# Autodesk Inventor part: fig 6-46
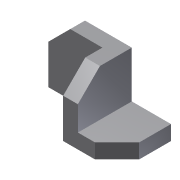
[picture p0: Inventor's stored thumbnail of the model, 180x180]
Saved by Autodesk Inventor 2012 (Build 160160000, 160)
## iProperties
Shininess: 77.0
Angle Display Precision: 2
Document Length Units: 11269
Document Angle Units: 11279
Document Time Units: 11290
Document Mass Units: 11283
Document Length Units Precision: 3
Document Angle Units Precision: 2
Created: 2001-12
Part Number: fig 6-46
Document SubType Name: Modeling
Designer: Renu Muthoo
Density: 1 g/cm^3
Material: Default
Density: 0.0
Volumn: 0.0
Area: 0.0
PropertySet Name: Model Information
Control State: 0
Master: False
Checked Out: False
Author: Renu Muthoo
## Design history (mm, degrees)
node "Sketch1"
sketch "Sketch2"
  geometry: L1 (16.794, 27.142)-(16.794, -22.858); L2 (16.794, -22.858)-(-27.206, -22.858); L3 (-27.206, -22.858)-(-27.206, -10.858); L4 (-27.206, -10.858)-(4.794, -10.858); L5 (4.794, -10.858)-(4.794, 27.142); L6 (4.794, 27.142)-(16.794, 27.142)
  constraints: 12 end point, 4 parallel, 2 perpendicular, 1 vertical
  dimensions: "d0" = 44 distance of L1.end L2.end; "d1" = 50 distance of L1.start L1.end; "d2" = 12 distance of L2.end L3.end
extrude "Extrusion1" new body sketch "Sketch2" distance "d3" = 44; taper "d4" = 0 deg
sketch "Sketch4"
  geometry: L1 (-16.794, -27.142)-(-16.794, 22.858) reference; L2 (27.206, 22.858)-(27.206, 10.858) reference; L3 (-16.794, -27.142)-(-61.001, -27.142); L4 (-61.001, -27.142)-(-61.001, 22.858); L5 (-61.001, 22.858)-(-16.794, 22.858)
  constraints: 6 end point, 2 perpendicular, 1 parallel
extrude "Extrusion3" join sketch "Sketch4" distance "d13" = 12; taper "d14" = 0 deg
chamfer "Chamfer3" distance "d15" = 18; stored, may be unused: second distance "d16" = 2, angle "d17" = 45 deg
body "Solid1"
